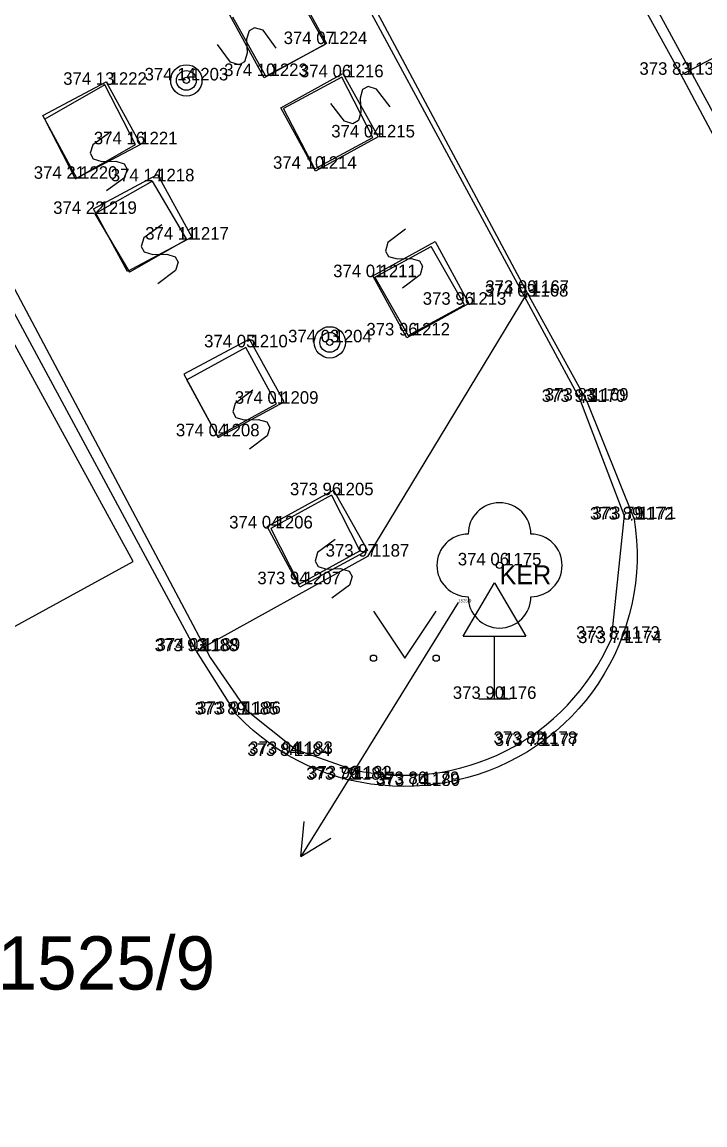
# Model space of a CAD drawing. Extents: x -601196 to -600262, y -1082523 to -1081922.
# Drawn here: x -600517.93 to -600507.03, y -1082160.04 to -1082142.44 of the extents above; entities that cross this region are included whole.
import ezdxf

# ---------------------------------------------------------------- set-up
doc = ezdxf.new("R2010")
doc.units = 0
for name, color, linetype in [('Vrstva 1', 7, 'Continuous'), ('Vrstva 10', 7, 'Continuous'), ('Vrstva 11', 7, 'Continuous'), ('Vrstva 2', 7, 'Continuous'), ('Vrstva 20', 7, 'Continuous'), ('Vrstva 22', 7, 'Continuous'), ('Vrstva 25', 7, 'Continuous'), ('Vrstva 3', 7, 'Continuous'), ('Vrstva 34', 7, 'Continuous'), ('Vrstva 36', 7, 'Continuous'), ('Vrstva 47', 7, 'Continuous'), ('Vrstva 63', 7, 'Continuous')]:
    doc.layers.add(name, color=color, linetype=linetype)

msp = doc.modelspace()

# ---------------------------------------------------------------- linework, layer by layer
at = {"layer": 'Vrstva 1'}
for p, q in [((-600513.09, -1082142.79), (-600513.09, -1082142.79)), ((-600516.61, -1082143.44), (-600516.61, -1082143.44)), ((-600515.31, -1082143.37), (-600515.31, -1082143.37)), ((-600514.04, -1082143.3), (-600514.04, -1082143.3)), ((-600512.83, -1082143.32), (-600512.83, -1082143.32)), ((-600507.41, -1082143.28), (-600507.41, -1082143.28)), ((-600512.33, -1082144.28), (-600512.33, -1082144.28)), ((-600516.12, -1082144.39), (-600516.12, -1082144.39)), ((-600513.26, -1082144.78), (-600513.26, -1082144.78)), ((-600517.08, -1082144.94), (-600517.08, -1082144.94)), ((-600515.85, -1082144.98), (-600515.85, -1082144.98)), ((-600516.77, -1082145.5), (-600516.77, -1082145.5)), ((-600515.3, -1082145.91), (-600515.3, -1082145.91)), ((-600512.3, -1082146.51), (-600512.3, -1082146.51)), ((-600509.87, -1082146.76), (-600509.87, -1082146.76)), ((-600510.87, -1082146.95), (-600510.87, -1082146.95)), ((-600509.88, -1082146.82), (-600509.88, -1082146.82)), ((-600511.77, -1082147.44), (-600511.77, -1082147.44)), ((-600514.36, -1082147.63), (-600514.36, -1082147.63)), ((-600513.02, -1082147.55), (-600513.02, -1082147.55)), ((-600513.87, -1082148.53), (-600513.87, -1082148.53)), ((-600508.97, -1082148.5), (-600508.97, -1082148.5)), ((-600508.92, -1082148.48), (-600508.92, -1082148.48)), ((-600514.81, -1082149.05), (-600514.81, -1082149.05)), ((-600512.99, -1082149.99), (-600512.99, -1082149.99)), ((-600508.2, -1082150.38), (-600508.2, -1082150.38)), ((-600508.16, -1082150.37), (-600508.16, -1082150.37)), ((-600513.96, -1082150.52), (-600513.96, -1082150.52)), ((-600512.42, -1082150.97), (-600512.42, -1082150.97)), ((-600510.31, -1082151.11), (-600510.31, -1082151.11)), ((-600513.51, -1082151.41), (-600513.51, -1082151.41)), ((-600508.42, -1082152.28), (-600508.42, -1082152.28)), ((-600508.39, -1082152.35), (-600508.39, -1082152.35)), ((-600515.15, -1082152.48), (-600515.15, -1082152.48)), ((-600515.12, -1082152.47), (-600515.12, -1082152.47)), ((-600510.39, -1082153.24), (-600510.39, -1082153.24)), ((-600514.51, -1082153.49), (-600514.51, -1082153.49)), ((-600514.47, -1082153.48), (-600514.47, -1082153.48)), ((-600509.74, -1082153.96), (-600509.74, -1082153.96)), ((-600509.72, -1082153.99), (-600509.72, -1082153.99)), ((-600513.67, -1082154.15), (-600513.67, -1082154.15)), ((-600513.64, -1082154.12), (-600513.64, -1082154.12)), ((-600512.7, -1082154.51), (-600512.7, -1082154.51)), ((-600512.73, -1082154.53), (-600512.73, -1082154.53)), ((-600511.62, -1082154.6), (-600511.62, -1082154.6)), ((-600511.61, -1082154.63), (-600511.61, -1082154.63))]:
    msp.add_line(p, q, dxfattribs=at)
at = {"layer": 'Vrstva 10'}
for p, q in [((-600514.72, -1082137.69), (-600509.87, -1082146.76)), ((-600507.41, -1082143.28), (-600509.3, -1082139.84)), ((-600515.15, -1082152.48), (-600521.24, -1082141.18)), ((-600506.3, -1082145.37), (-600507.41, -1082143.28)), ((-600509.87, -1082146.76), (-600508.92, -1082148.48)), ((-600508.92, -1082148.48), (-600508.16, -1082150.37)), ((-600514.51, -1082153.49), (-600515.15, -1082152.48))]:
    msp.add_line(p, q, dxfattribs=at)
for points in [[(-600508.16, -1082150.37), (-600508.137, -1082150.54), (-600508.122, -1082150.71), (-600508.114, -1082150.881), (-600508.115, -1082151.053), (-600508.124, -1082151.224), (-600508.14, -1082151.394), (-600508.165, -1082151.564), (-600508.197, -1082151.732), (-600508.238, -1082151.899), (-600508.286, -1082152.063), (-600508.341, -1082152.225), (-600508.405, -1082152.385), (-600508.475, -1082152.541), (-600508.553, -1082152.694), (-600508.637, -1082152.843), (-600508.729, -1082152.988), (-600508.827, -1082153.128), (-600508.932, -1082153.264), (-600509.043, -1082153.395), (-600509.16, -1082153.52), (-600509.282, -1082153.64), (-600509.41, -1082153.754), (-600509.543, -1082153.862), (-600509.681, -1082153.963), (-600509.72, -1082153.99)], [(-600512.73, -1082154.53), (-600512.896, -1082154.484), (-600513.06, -1082154.43), (-600513.22, -1082154.369), (-600513.378, -1082154.301), (-600513.533, -1082154.225), (-600513.684, -1082154.142), (-600513.831, -1082154.052), (-600513.973, -1082153.956), (-600514.111, -1082153.852), (-600514.244, -1082153.743), (-600514.372, -1082153.628), (-600514.494, -1082153.506), (-600514.51, -1082153.49)], [(-600509.72, -1082153.99), (-600509.866, -1082154.084), (-600510.016, -1082154.17), (-600510.17, -1082154.25), (-600510.328, -1082154.323), (-600510.488, -1082154.388), (-600510.652, -1082154.447), (-600510.818, -1082154.497), (-600510.986, -1082154.54), (-600511.156, -1082154.575), (-600511.327, -1082154.602), (-600511.5, -1082154.622), (-600511.673, -1082154.633), (-600511.846, -1082154.637), (-600512.019, -1082154.632), (-600512.192, -1082154.62), (-600512.364, -1082154.6), (-600512.535, -1082154.572), (-600512.705, -1082154.536), (-600512.73, -1082154.53)]]:
    msp.add_lwpolyline(points, dxfattribs=at)
at = {"layer": 'Vrstva 11'}
for p, q in [((-600507.41, -1082143.28), (-600503.19, -1082141.06)), ((-600513.09, -1082142.79), (-600513.62, -1082141.85)), ((-600514.04, -1082143.3), (-600514.57, -1082142.36)), ((-600514.04, -1082143.3), (-600513.09, -1082142.79)), ((-600516.61, -1082143.44), (-600517.57, -1082143.99)), ((-600516.12, -1082144.39), (-600516.61, -1082143.44)), ((-600512.83, -1082143.32), (-600513.76, -1082143.82)), ((-600512.33, -1082144.28), (-600512.83, -1082143.32)), ((-600513.26, -1082144.78), (-600513.76, -1082143.82)), ((-600517.08, -1082144.94), (-600517.57, -1082143.99)), ((-600513.26, -1082144.78), (-600512.33, -1082144.28)), ((-600517.08, -1082144.94), (-600516.12, -1082144.39)), ((-600515.85, -1082144.98), (-600516.77, -1082145.5)), ((-600515.3, -1082145.91), (-600515.85, -1082144.98)), ((-600516.77, -1082145.5), (-600516.22, -1082146.43)), ((-600515.3, -1082145.91), (-600516.22, -1082146.43)), ((-600512.3, -1082146.51), (-600511.4, -1082146.02)), ((-600510.87, -1082146.95), (-600511.4, -1082146.02)), ((-600512.3, -1082146.51), (-600511.77, -1082147.44)), ((-600509.87, -1082146.76), (-600512.42, -1082150.97)), ((-600511.77, -1082147.44), (-600510.87, -1082146.95)), ((-600514.36, -1082147.63), (-600515.3, -1082148.15)), ((-600513.87, -1082148.53), (-600514.36, -1082147.63)), ((-600514.81, -1082149.05), (-600515.3, -1082148.15)), ((-600514.81, -1082149.05), (-600513.87, -1082148.53)), ((-600512.99, -1082149.99), (-600513.96, -1082150.52)), ((-600512.99, -1082149.99), (-600512.54, -1082150.88)), ((-600513.96, -1082150.52), (-600513.51, -1082151.41)), ((-600512.42, -1082150.97), (-600515.15, -1082152.48)), ((-600513.51, -1082151.41), (-600512.54, -1082150.88))]:
    msp.add_line(p, q, dxfattribs=at)
at = {"layer": 'Vrstva 20'}
for p, q in [((-600509.89, -1082146.82), (-600509.87, -1082146.82)), ((-600509.88, -1082146.805), (-600509.88, -1082146.82)), ((-600509.88, -1082146.835), (-600509.88, -1082146.82)), ((-600508.98, -1082148.5), (-600508.96, -1082148.5)), ((-600508.97, -1082148.485), (-600508.97, -1082148.5)), ((-600508.97, -1082148.515), (-600508.97, -1082148.5)), ((-600508.21, -1082150.38), (-600508.19, -1082150.38)), ((-600508.2, -1082150.365), (-600508.2, -1082150.38)), ((-600508.2, -1082150.395), (-600508.2, -1082150.38)), ((-600508.43, -1082152.28), (-600508.41, -1082152.28)), ((-600508.42, -1082152.265), (-600508.42, -1082152.28)), ((-600508.42, -1082152.295), (-600508.42, -1082152.28)), ((-600515.13, -1082152.47), (-600515.11, -1082152.47)), ((-600515.12, -1082152.455), (-600515.12, -1082152.47)), ((-600515.12, -1082152.485), (-600515.12, -1082152.47)), ((-600514.47, -1082153.465), (-600514.47, -1082153.48)), ((-600514.48, -1082153.48), (-600514.46, -1082153.48)), ((-600514.47, -1082153.495), (-600514.47, -1082153.48)), ((-600509.75, -1082153.96), (-600509.73, -1082153.96)), ((-600509.74, -1082153.945), (-600509.74, -1082153.96)), ((-600509.74, -1082153.975), (-600509.74, -1082153.96)), ((-600513.65, -1082154.12), (-600513.63, -1082154.12)), ((-600513.64, -1082154.105), (-600513.64, -1082154.12)), ((-600513.64, -1082154.135), (-600513.64, -1082154.12)), ((-600512.71, -1082154.51), (-600512.69, -1082154.51)), ((-600512.7, -1082154.495), (-600512.7, -1082154.51)), ((-600512.7, -1082154.525), (-600512.7, -1082154.51)), ((-600511.63, -1082154.6), (-600511.61, -1082154.6)), ((-600511.62, -1082154.585), (-600511.62, -1082154.6)), ((-600511.62, -1082154.615), (-600511.62, -1082154.6))]:
    msp.add_line(p, q, dxfattribs=at)
at = {"layer": 'Vrstva 22'}
msp.add_circle((-600510.31, -1082151.11), 0.05, dxfattribs=at)
for centre, start, end in [((-600510.31, -1082150.61), 0, 180), ((-600510.81, -1082151.11), 90, 270), ((-600509.81, -1082151.11), 270, 90), ((-600510.31, -1082151.61), 180, 0)]:
    msp.add_arc(centre, 0.5, start, end, dxfattribs=at)
at = {"layer": 'Vrstva 25'}
for centre, radius in [((-600515.31, -1082143.37), 0.25), ((-600515.31, -1082143.37), 0.158), ((-600515.31, -1082143.37), 0.05), ((-600513.02, -1082147.55), 0.25), ((-600513.02, -1082147.55), 0.158), ((-600513.02, -1082147.55), 0.05)]:
    msp.add_circle(centre, radius, dxfattribs=at)
at = {"layer": 'Vrstva 34'}
for p, q in [((-600510.89, -1082152.24), (-600510.39, -1082151.39)), ((-600510.39, -1082151.39), (-600509.89, -1082152.24)), ((-600510.89, -1082152.24), (-600509.89, -1082152.24)), ((-600510.39, -1082153.24), (-600510.39, -1082152.24)), ((-600510.64, -1082153.24), (-600510.14, -1082153.24))]:
    msp.add_line(p, q, dxfattribs=at)
at = {"layer": 'Vrstva 36'}
for p, q in [((-600512.322, -1082151.84), (-600511.822, -1082152.59)), ((-600511.822, -1082152.59), (-600511.322, -1082151.84))]:
    msp.add_line(p, q, dxfattribs=at)
for centre in [(-600512.322, -1082152.59), (-600511.322, -1082152.59)]:
    msp.add_circle(centre, 0.05, dxfattribs=at)
at = {"layer": 'Vrstva 47'}
for p, q in [((-600515.03, -1082128.91), (-600505.95, -1082145.64)), ((-600509.03, -1082148.45), (-600518.52, -1082130.88)), ((-600522.29, -1082138.73), (-600514.93, -1082152.58)), ((-600516.16, -1082151.05), (-600522.62, -1082139.23)), ((-600513.62, -1082141.78), (-600513.07, -1082142.78)), ((-600514.07, -1082143.33), (-600514.62, -1082142.32)), ((-600514.221, -1082142.529), (-600514.308, -1082142.577)), ((-600514.085, -1082142.569), (-600514.221, -1082142.529)), ((-600514.308, -1082142.577), (-600514.348, -1082142.713)), ((-600514.348, -1082142.713), (-600514.341, -1082142.936)), ((-600513.874, -1082142.853), (-600514.085, -1082142.569)), ((-600514.604, -1082143.08), (-600514.815, -1082142.796)), ((-600513.07, -1082142.78), (-600514.07, -1082143.33)), ((-600514.468, -1082143.12), (-600514.604, -1082143.08)), ((-600514.381, -1082143.072), (-600514.468, -1082143.12)), ((-600514.341, -1082142.936), (-600514.381, -1082143.072)), ((-600513.8, -1082143.81), (-600512.81, -1082143.26)), ((-600512.81, -1082143.26), (-600512.25, -1082144.27)), ((-600517.6, -1082143.93), (-600516.59, -1082143.39)), ((-600516.59, -1082143.39), (-600516.04, -1082144.39)), ((-600512.495, -1082143.517), (-600512.534, -1082143.653)), ((-600512.408, -1082143.468), (-600512.495, -1082143.517)), ((-600512.272, -1082143.507), (-600512.408, -1082143.468)), ((-600512.058, -1082143.789), (-600512.272, -1082143.507)), ((-600512.787, -1082144.022), (-600513.001, -1082143.74)), ((-600512.534, -1082143.653), (-600512.525, -1082143.876)), ((-600517.06, -1082144.93), (-600517.6, -1082143.93)), ((-600513.25, -1082144.82), (-600513.8, -1082143.81)), ((-600512.525, -1082143.876), (-600512.564, -1082144.012)), ((-600512.651, -1082144.061), (-600512.787, -1082144.022)), ((-600512.564, -1082144.012), (-600512.651, -1082144.061)), ((-600516.516, -1082144.189), (-600516.802, -1082144.397)), ((-600512.25, -1082144.27), (-600513.25, -1082144.82)), ((-600516.04, -1082144.39), (-600517.06, -1082144.93)), ((-600516.802, -1082144.397), (-600516.843, -1082144.532)), ((-600516.843, -1082144.532), (-600516.796, -1082144.621)), ((-600516.796, -1082144.621), (-600516.661, -1082144.662)), ((-600516.661, -1082144.662), (-600516.438, -1082144.657)), ((-600516.438, -1082144.657), (-600516.303, -1082144.699)), ((-600516.303, -1082144.699), (-600516.256, -1082144.787)), ((-600516.256, -1082144.787), (-600516.297, -1082144.922)), ((-600516.79, -1082145.42), (-600515.77, -1082144.87)), ((-600516.297, -1082144.922), (-600516.583, -1082145.13)), ((-600515.77, -1082144.87), (-600515.22, -1082145.87)), ((-600516.25, -1082146.42), (-600516.79, -1082145.42)), ((-600515.702, -1082145.674), (-600515.988, -1082145.883)), ((-600515.22, -1082145.87), (-600516.25, -1082146.42)), ((-600515.988, -1082145.883), (-600516.029, -1082146.018)), ((-600511.81, -1082145.743), (-600512.092, -1082145.957)), ((-600516.029, -1082146.018), (-600515.982, -1082146.106)), ((-600512.33, -1082146.49), (-600511.34, -1082145.94)), ((-600512.092, -1082145.957), (-600512.131, -1082146.093)), ((-600511.34, -1082145.94), (-600510.8, -1082146.93)), ((-600515.982, -1082146.106), (-600515.846, -1082146.148)), ((-600515.846, -1082146.148), (-600515.623, -1082146.142)), ((-600515.623, -1082146.142), (-600515.487, -1082146.183)), ((-600515.487, -1082146.183), (-600515.44, -1082146.271)), ((-600512.131, -1082146.093), (-600512.082, -1082146.181)), ((-600512.082, -1082146.181), (-600511.946, -1082146.219)), ((-600511.946, -1082146.219), (-600511.723, -1082146.21)), ((-600511.723, -1082146.21), (-600511.587, -1082146.249)), ((-600511.587, -1082146.249), (-600511.538, -1082146.336)), ((-600515.481, -1082146.406), (-600515.767, -1082146.615)), ((-600515.44, -1082146.271), (-600515.481, -1082146.406)), ((-600511.538, -1082146.336), (-600511.577, -1082146.472)), ((-600511.79, -1082147.48), (-600512.33, -1082146.49)), ((-600511.577, -1082146.472), (-600511.859, -1082146.686)), ((-600510.8, -1082146.93), (-600511.79, -1082147.48)), ((-600514.3, -1082147.5), (-600515.35, -1082148.06)), ((-600513.75, -1082148.5), (-600514.3, -1082147.5)), ((-600515.35, -1082148.06), (-600514.8, -1082149.07)), ((-600514.246, -1082148.314), (-600514.529, -1082148.525)), ((-600514.8, -1082149.07), (-600513.75, -1082148.5)), ((-600514.529, -1082148.525), (-600514.57, -1082148.66)), ((-600508.32, -1082150.31), (-600509.03, -1082148.45)), ((-600514.57, -1082148.66), (-600514.522, -1082148.748)), ((-600514.522, -1082148.748), (-600514.386, -1082148.788)), ((-600514.386, -1082148.788), (-600514.163, -1082148.781)), ((-600514.163, -1082148.781), (-600514.027, -1082148.821)), ((-600514.027, -1082148.821), (-600513.979, -1082148.909)), ((-600514.02, -1082149.044), (-600514.303, -1082149.255)), ((-600513.979, -1082148.909), (-600514.02, -1082149.044)), ((-600514.02, -1082150.49), (-600512.96, -1082149.91)), ((-600512.96, -1082149.91), (-600512.42, -1082150.87)), ((-600508.32, -1082150.31), (-600508.53, -1082152.29)), ((-600513.5, -1082151.46), (-600514.02, -1082150.49)), ((-600512.932, -1082150.694), (-600513.215, -1082150.905)), ((-600512.42, -1082150.87), (-600513.5, -1082151.46)), ((-600513.215, -1082150.905), (-600513.255, -1082151.041)), ((-600532.64, -1082160.04), (-600516.16, -1082151.05)), ((-600513.255, -1082151.041), (-600513.207, -1082151.129)), ((-600513.207, -1082151.129), (-600513.071, -1082151.169)), ((-600513.071, -1082151.169), (-600512.848, -1082151.16)), ((-600512.848, -1082151.16), (-600512.712, -1082151.2)), ((-600512.712, -1082151.2), (-600512.664, -1082151.288)), ((-600512.664, -1082151.288), (-600512.704, -1082151.424)), ((-600512.704, -1082151.424), (-600512.987, -1082151.635)), ((-600510.97, -1082151.7), (-600512.69, -1082154.48)), ((-600514.93, -1082152.58), (-600514.35, -1082153.42)), ((-600514.35, -1082153.42), (-600513.56, -1082154.05)), ((-600513.56, -1082154.05), (-600512.64, -1082154.37)), ((-600512.69, -1082154.48), (-600513.48, -1082155.754)), ((-600513.48, -1082155.754), (-600513.429, -1082155.198)), ((-600513.48, -1082155.754), (-600513.004, -1082155.461))]:
    msp.add_line(p, q, dxfattribs=at)
msp.add_arc((-600511.84, -1082150.85), 3.61, 257.1993, 336.4871, dxfattribs=at)

# ---------------------------------------------------------------- texts
at = {"layer": 'Vrstva 2'}
for s, p in [(' 1224', (-600513.09, -1082142.79)), (' 1132', (-600507.41, -1082143.28)), (' 1222', (-600516.61, -1082143.44)), (' 1203', (-600515.31, -1082143.37)), (' 1223', (-600514.04, -1082143.3)), (' 1216', (-600512.83, -1082143.32)), (' 1215', (-600512.33, -1082144.28)), (' 1221', (-600516.12, -1082144.39)), (' 1214', (-600513.26, -1082144.78)), (' 1220', (-600517.08, -1082144.94)), (' 1218', (-600515.85, -1082144.98)), (' 1219', (-600516.77, -1082145.5)), (' 1217', (-600515.3, -1082145.91)), (' 1211', (-600512.3, -1082146.51)), (' 1167', (-600509.87, -1082146.76)), (' 1213', (-600510.87, -1082146.95)), (' 1168', (-600509.88, -1082146.82)), (' 1212', (-600511.77, -1082147.44)), (' 1210', (-600514.36, -1082147.63)), (' 1204', (-600513.02, -1082147.55)), (' 1209', (-600513.87, -1082148.53)), (' 1170', (-600508.97, -1082148.5)), (' 1169', (-600508.92, -1082148.48)), (' 1208', (-600514.81, -1082149.05)), (' 1205', (-600512.99, -1082149.99)), (' 1172', (-600508.2, -1082150.38)), (' 1171', (-600508.16, -1082150.37)), (' 1206', (-600513.96, -1082150.52)), (' 1187', (-600512.42, -1082150.97)), (' 1175', (-600510.31, -1082151.11)), (' 1207', (-600513.51, -1082151.41)), (' 1173', (-600508.42, -1082152.28)), (' 1174', (-600508.39, -1082152.35)), (' 1188', (-600515.15, -1082152.48)), (' 1189', (-600515.12, -1082152.47)), (' 1176', (-600510.39, -1082153.24)), (' 1185', (-600514.51, -1082153.49)), (' 1186', (-600514.47, -1082153.48)), (' 1178', (-600509.74, -1082153.96)), (' 1177', (-600509.72, -1082153.99)), (' 1184', (-600513.67, -1082154.15)), (' 1183', (-600513.64, -1082154.12)), (' 1181', (-600512.73, -1082154.53)), (' 1182', (-600512.7, -1082154.51)), (' 1179', (-600511.62, -1082154.6)), (' 1180', (-600511.61, -1082154.63))]:
    msp.add_text(s, height=0.2, dxfattribs=at).set_placement(p)
at = {"layer": 'Vrstva 3'}
for s, p in [('374 07 ', (-600513.756, -1082142.79)), ('373 83 ', (-600508.076, -1082143.28)), ('374 13 ', (-600517.276, -1082143.44)), ('374 14 ', (-600515.976, -1082143.37)), ('374 10 ', (-600514.706, -1082143.3)), ('374 06 ', (-600513.496, -1082143.32)), ('374 04 ', (-600512.996, -1082144.28)), ('374 16 ', (-600516.786, -1082144.39)), ('374 10 ', (-600513.926, -1082144.78)), ('374 21 ', (-600517.746, -1082144.94)), ('374 14 ', (-600516.516, -1082144.98)), ('374 22 ', (-600517.436, -1082145.5)), ('374 11 ', (-600515.966, -1082145.91)), ('374 01 ', (-600512.966, -1082146.51)), ('373 90 ', (-600510.536, -1082146.76)), ('373 96 ', (-600511.536, -1082146.95)), ('374 03 ', (-600510.546, -1082146.82)), ('373 96 ', (-600512.436, -1082147.44)), ('374 05 ', (-600515.026, -1082147.63)), ('374 03 ', (-600513.686, -1082147.55)), ('374 01 ', (-600514.536, -1082148.53)), ('373 93 ', (-600509.636, -1082148.5)), ('373 83 ', (-600509.586, -1082148.48)), ('374 04 ', (-600515.476, -1082149.05)), ('373 96 ', (-600513.656, -1082149.99)), ('373 89 ', (-600508.866, -1082150.38)), ('373 79 ', (-600508.826, -1082150.37)), ('374 04 ', (-600514.626, -1082150.52)), ('373 97 ', (-600513.086, -1082150.97)), ('374 06 ', (-600510.976, -1082151.11)), ('373 94 ', (-600514.176, -1082151.41)), ('373 87 ', (-600509.086, -1082152.28)), ('373 74 ', (-600509.056, -1082152.35)), ('373 93 ', (-600515.816, -1082152.48)), ('374 02 ', (-600515.786, -1082152.47)), ('373 90 ', (-600511.056, -1082153.24)), ('373 89 ', (-600515.176, -1082153.49)), ('373 97 ', (-600515.136, -1082153.48)), ('373 82 ', (-600510.406, -1082153.96)), ('373 75 ', (-600510.386, -1082153.99)), ('373 84 ', (-600514.336, -1082154.15)), ('373 94 ', (-600514.306, -1082154.12)), ('373 79 ', (-600513.396, -1082154.53)), ('373 90 ', (-600513.366, -1082154.51)), ('373 86 ', (-600512.286, -1082154.6)), ('373 74 ', (-600512.276, -1082154.63))]:
    msp.add_text(s, height=0.2, dxfattribs=at).set_placement(p)
at = {"layer": 'Vrstva 47'}
for height, p in [(0.05, (-600510.97, -1082151.7)), (0.85, (-600518.326, -1082157.88))]:
    msp.add_text('1525/9', height=height, dxfattribs=at).set_placement(p)
at = {"layer": 'Vrstva 63'}
msp.add_text('KER', height=0.3, dxfattribs=at).set_placement((-600510.31, -1082151.41))

doc.saveas('drawing.dxf')
